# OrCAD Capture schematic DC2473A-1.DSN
size Custom; title: DUAL DIFFERENTIAL AMPLIFIERS/ADC DRIVERS; rev: 1; company: TM
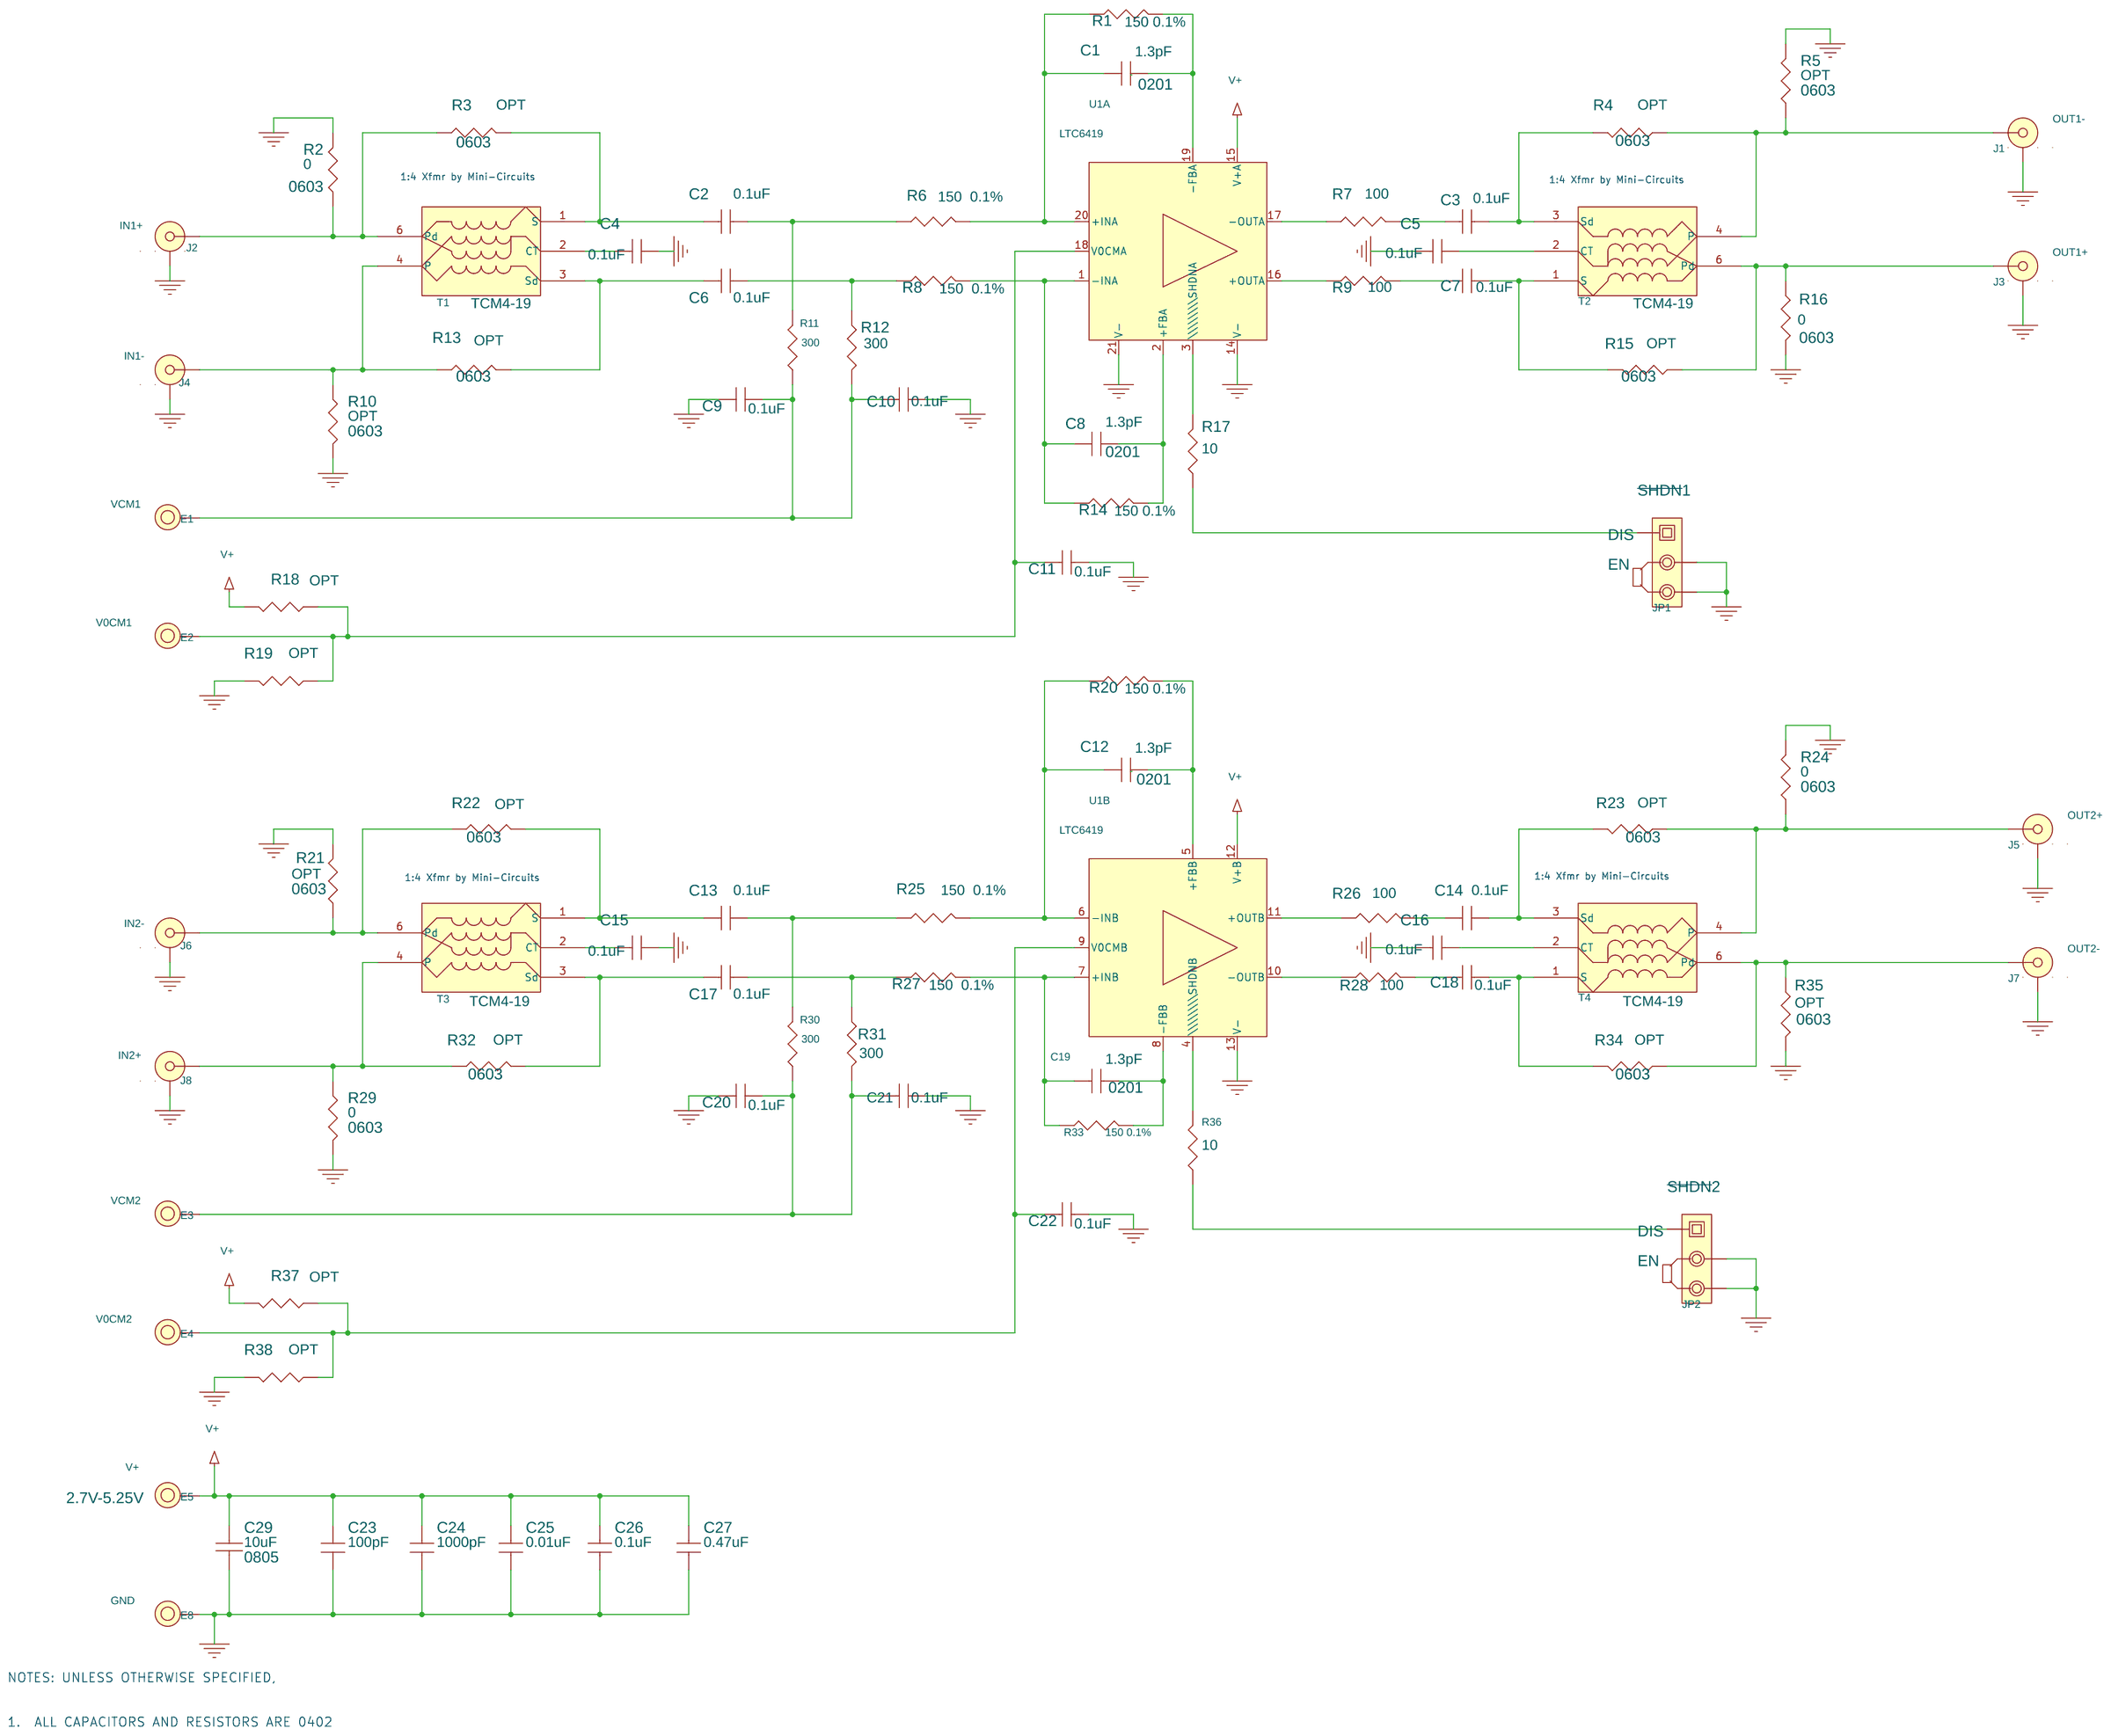
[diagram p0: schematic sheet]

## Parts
C1  1.3pF  [0201]
C2  0.1uF  [0402]
C3  0.1uF  [0402]
C4  0.1uF  [0402]
C5  0.1uF  [0402]
C6  0.1uF  [0402]
C7  0.1uF  [0402]
C8  1.3pF  [0201]
C9  0.1uF  [0402]
C10  0.1uF  [0402]
C11  0.1uF  [0402]
C12  1.3pF  [0201]
C13  0.1uF  [0402]
C14  0.1uF  [0402]
C15  0.1uF  [0402]
C16  0.1uF  [0402]
C17  0.1uF  [0402]
C18  0.1uF  [0402]
C19  1.3pF  [0201]
C20  0.1uF  [0402]
C21  0.1uF  [0402]
C22  0.1uF  [0402]
C23  100pF  [0402]
C24  1000pF  [0402]
C25  0.01uF  [0402]
C26  0.1uF  [0402]
C27  0.47uF  [0402]
C29  10uF  [0805]
E1  MILL MAX 2501  [MILLMAX2308]
E2  MILL MAX 2501  [MILLMAX2308]
E3  MILL MAX 2501  [MILLMAX2308]
E4  MILL MAX 2501  [MILLMAX2308]
E5  MILL MAX 2501  [MILLMAX2308]
E8  MILL MAX 2501  [MILLMAX2308]
J1  OUT1-  [CON\SMA-END]
J2  IN1+  [CON\SMA-END]
J3  OUT1+  [CON\SMA-END]
J4  IN1-  [CON\SMA-END]
J5  OUT2+  [CON\SMA-END]
J6  IN2-  [CON\SMA-END]
J7  OUT2-  [CON\SMA-END]
J8  IN2+  [CON\SMA-END]
JP1  3 Pins 2mm Ctrs.  [Samtec\TMM-103-02-L-S]
JP2  3 Pins 2mm Ctrs.  [Samtec\TMM-103-02-L-S]
R1  150 0.1%  [0402]
R2  0  [0603]
R3  OPT  [0603]
R4  OPT  [0603]
R5  OPT  [0603]
R6  150  0.1%  [0402]
R7  100  [0402]
R8  150  0.1%  [0402]
R9  100  [0402]
R10  OPT  [0603]
R11  300  [0402]
R12  300  [0402]
R13  OPT  [0603]
R14  150 0.1%  [0402]
R15  OPT  [0603]
R16  0  [0603]
R17  10  [0402]
R18  OPT  [0402]
R19  OPT  [0402]
R20  150 0.1%  [0402]
R21  OPT  [0603]
R22  OPT  [0603]
R23  OPT  [0603]
R24  0  [0603]
R25  150  0.1%  [0402]
R26  100  [0402]
R27  150  0.1%  [0402]
R28  100  [0402]
R29  0  [0603]
R30  300  [0402]
R31  300  [0402]
R32  OPT  [0603]
R33  150 0.1%  [0402]
R34  OPT  [0603]
R35  OPT  [0603]
R36  10  [0402]
R37  OPT  [0402]
R38  OPT  [0402]
T1  TCM4-19  [TRANS-TCM4-19+]
T2  TCM4-19  [TRANS-TCM4-19+]
T3  TCM4-19  [TRANS-TCM4-19+]
T4  TCM4-19  [TRANS-TCM4-19+]
U1  LTC6419  [QFN-3X4-20PIN]  (sections A,B)
XJP1  2mm Ctrs.
XJP2  2mm Ctrs.

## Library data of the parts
C1-C27 = CAP0402
C29 = CAP_NP: Part Type: GRM21BR61A106K
E1 = TURRET,_.093_MTG_HOLE: 1: 1.2V-3.3V; VOLTAGE: VCM1
E2 = TURRET,_.093_MTG_HOLE: 1: 1.2V-3.3V; VOLTAGE: V0CM1
E3 = TURRET,_.093_MTG_HOLE: 1: 1.2V-3.3V; VOLTAGE: VCM2
E4 = TURRET,_.093_MTG_HOLE: 1: 1.2V-3.3V; VOLTAGE: V0CM2
E5 = TURRET,_.093_MTG_HOLE: 1: 2.7V-5.25V; VOLTAGE: V+
E8 = TURRET,_.093_MTG_HOLE: 1: 1.2V-3.3V; VOLTAGE: GND
J1-J8 = CON_SMA-END_3: CONN, BNC, SMA 50-OHM EDGE-LANCH; Part Number: E.F.JOHNSON, 142-0701-851
JP1 = HEADER-3X1_5: 1: DIS; 2: EN; 4th Part Field: SHDN1
JP2 = HEADER-3X1_5: 1: DIS; 2: EN; 4th Part Field: SHDN2
R1-R38 = RESISTOR
T1-T4 = Trans_TCM4-19_1: Part Type: TranSMT
U1 = LTC6419EUDC
XJP1 XJP2 = SHUNT,_2MM

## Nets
GND: C4.2 C5.2 C9.1 C10.2 C11.2 C15.2 C16.2 C20.1 C21.2 C22.2 C23.1 C24.2 C25.1 C26.1 C27.1 C29.2 E8.1 J1.2(GND) J1.3(GND) J1.4(GND) J1.5(GND) J2.2(GND) J2.3(GND) J2.4(GND) J2.5(GND) J3.2(GND) J3.3(GND) J3.4(GND) J3.5(GND) J4.2(GND) J4.3(GND) J4.4(GND) J4.5(GND) J5.2(GND) J5.3(GND) J5.4(GND) J5.5(GND) J6.2(GND) J6.3(GND) J6.4(GND) J6.5(GND) J7.2(GND) J7.3(GND) J7.4(GND) J7.5(GND) J8.2(GND) J8.3(GND) J8.4(GND) J8.5(GND) JP1.2 JP1.3 JP2.2 JP2.3 R2.1 R5.2 R10.2 R16.1 R19.1 R21.1 R24.2 R29.2 R35.1 R38.1 U1.13(V-) U1.14(V-) U1.21(V-)
V+: C23.2 C24.1 C25.2 C26.2 C27.2 C29.1 E5.1 R18.1 R37.1 U1.12(V+B) U1.15(V+A)
N25894151: C6.1 R13.2 T1.3(Sd)
N25894182: J4.1(CENTER) R10.1 R13.1 T1.4(P)
N25894337: C2.1 R3.2 T1.1(S)
N25894391: C2.2 R6.1 R11.2
N25894393: C6.2 R8.1 R12.2
N25894469: C9.2 C10.1 E1.1 R11.1 R12.1
N25895047: C4.1 T1.2(CT)
N25897727: J2.1(CENTER) R2.2 R3.1 T1.6(Pd)
N25903043: C1.1 R1.1 R6.2 U1.20(+INA)
N25903046: C8.1 R8.2 R14.1 U1.1(-INA)
N25903664: C11.1 E2.1 R18.2 R19.2 U1.18(V0CMA)
N25905565: C8.2 R14.2 U1.2(+FBA)
N25905829: C1.2 R1.2 U1.19(-FBA)
N25906544: C3.1 R7.2
N25906581: C7.1 R9.2
N25906856: J1.1(CENTER) R4.1 R5.1 T2.4(P)
N25906864: C3.2 R4.2 T2.3(Sd)
N25906897: C7.2 R15.2 T2.1(S)
N25906956: J3.1(CENTER) R15.1 R16.2 T2.6(Pd)
N25907445: C5.1 T2.2(CT)
N25909054: C14.1 R26.2
N25909056: C18.1 R28.2
N25909058: J5.1(CENTER) R23.1 R24.1 T4.4(P)
N25909062: C14.2 R23.2 T4.3(Sd)
N25909076: C18.2 R34.2 T4.1(S)
N25909137: J7.1(CENTER) R34.1 R35.2 T4.6(Pd)
N25909185: C16.1 T4.2(CT)
N25909754: C12.1 R20.1 R25.2 U1.6(-INB)
N25909756: C19.1 R27.2 R33.1 U1.7(+INB)
N25909782: J8.1(CENTER) R29.1 R32.1 T3.4(P)
N25909786: C22.1 E4.1 R37.2 R38.2 U1.9(V0CMB)
N25909816: C20.2 C21.1 E3.1 R30.1 R31.1
N25909923: C19.2 R33.2 U1.8(-FBB)
N25909981: C12.2 R20.2 U1.5(+FBB)
N25909999: C17.1 R32.2 T3.3(Sd)
N25910029: C13.1 R22.2 T3.1(S)
N25910033: C13.2 R25.1 R30.2
N25910035: C17.2 R27.1 R31.2
N25910142: C15.1 T3.2(CT)
N25910168: J6.1(CENTER) R21.2 R22.1 T3.6(Pd)
N25928625: JP1.1 R17.1
N25928747: JP2.1 R36.1
N25955067: R26.1 U1.11(+OUTB)
N25955070: R28.1 U1.10(-OUTB)
N25955228: R36.2 U1.4(\\\\\\\\SHDNB)
N25955357: R7.1 U1.17(-OUTA)
N25955360: R9.1 U1.16(+OUTA)
N25955475: R17.2 U1.3(\\\\\\\\SHDNA)

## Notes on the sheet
- 1:4 Xfmr by Mini-Circuits
- 1:4 Xfmr by Mini-Circuits
- 1:4 Xfmr by Mini-Circuits
- 1:4 Xfmr by Mini-Circuits
- NOTES: UNLESS OTHERWISE SPECIFIED,
- 1.  ALL CAPACITORS AND RESISTORS ARE 0402
